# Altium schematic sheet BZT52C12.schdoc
size 127 x 101 mm
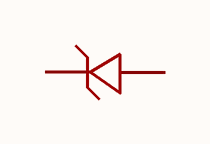
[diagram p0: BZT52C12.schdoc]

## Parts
D?  bzt52c12_c173429  [SOD-123_L2.7-W1.6-LS3.7-RD]  (value not drawn)

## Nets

Not connected (* = marked no-connect by the designer): D? 1(K) 2(A)

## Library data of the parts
D? = bzt52c12_c173429: 二极管配置:1个独立式;稳压值(标称值):12V;稳压值(范围值):11.4V~12.6V;耗散功率(Pd):500mW;; Manufacturer: MDD(辰达半导体); AddInBom: yes; ModelId: ad7e39f9e5534b3c96ffdc5532ebb493; ModelName: SOD-123_L2.7-W1.6-H1.4-LS3.7; ModelTransform: 146.026,62.992,0,180,0,0,0.0005,0,0; Diode Configuration: 1个独立式; Zener Voltage(Nom): 12V; Reverse Leakage Current (Ir): 100nA@9V; Pd - Power Dissipation: 500mW; Impedance(Zzt): 35Ω; Tolerance: ±5%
